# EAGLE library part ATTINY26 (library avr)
MICROCONTROLLER 2 Kbytes FLASH 128 bytes SRAM 128 bytes EEPROM USI 10-channel 10 bit ADC
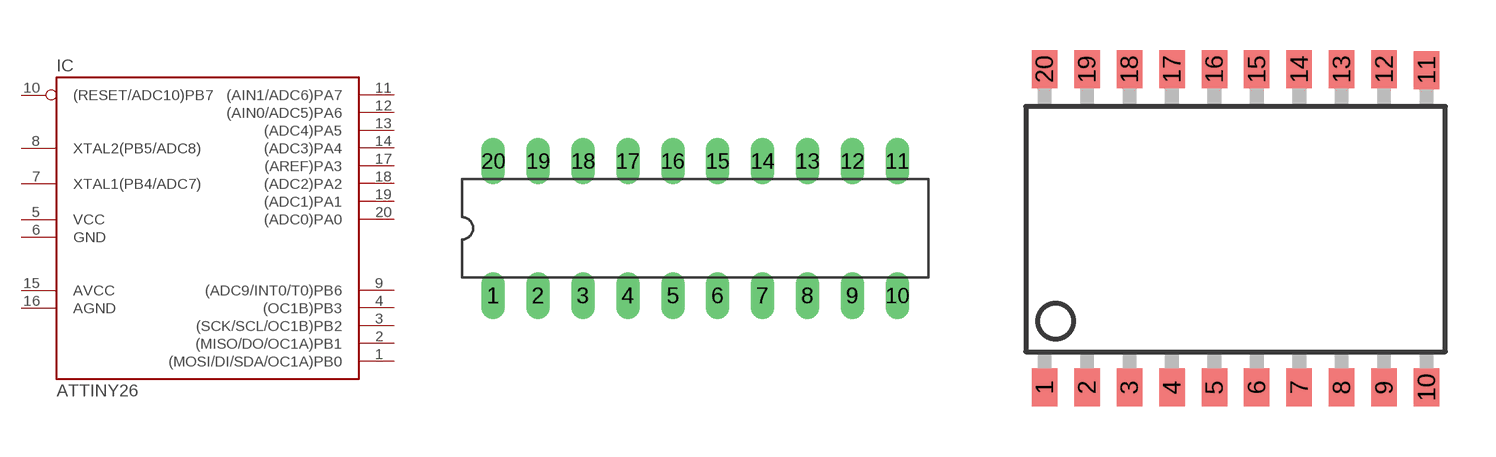
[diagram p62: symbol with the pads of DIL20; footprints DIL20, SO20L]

Designator prefix IC

## ATTINY26-16P, ATTINY26L-8P  [DIL20]
1  (MOSI/DI/SDA/OC1A)PB0
2  (MISO/DO/OC1A)PB1
3  (SCK/SCL/OC1B)PB2
4  (OC1B)PB3
5  VCC  pwr
6  GND  pwr
7  XTAL1(PB4/ADC7)
8  XTAL2(PB5/ADC8)
9  (ADC9/INT0/T0)PB6
10  (RESET/ADC10)PB7
11  (AIN1/ADC6)PA7
12  (AIN0/ADC5)PA6
13  (ADC4)PA5
14  (ADC3)PA4
15  AVCC  pwr
16  AGND  pwr
17  (AREF)PA3
18  (ADC2)PA2
19  (ADC1)PA1
20  (ADC0)PA0

## ATTINY26-16S, ATTINY26L-8S  [SO20L]
Pads as for DIL20

## Footprint DIL20 (pad centres in mm)
Dual In Line
drill 0.813 long: 1 -11.43,-3.81; 2 -8.89,-3.81; 3 -6.35,-3.81; 4 -3.81,-3.81; 5 -1.27,-3.81; 6 1.27,-3.81; 7 3.81,-3.81; 8 6.35,-3.81; 9 8.89,-3.81; 10 11.43,-3.81; 11 11.43,3.81; 12 8.89,3.81; 13 6.35,3.81; 14 3.81,3.81; 15 1.27,3.81; 16 -1.27,3.81; 17 -3.81,3.81; 18 -6.35,3.81; 19 -8.89,3.81; 20 -11.43,3.81

## Footprint SO20L (pad centres in mm)
Small Outline Package
smd 0.762 x 1.143: 1 -5.08,-5.131; 2 -3.81,-5.131; 3 -2.54,-5.131; 4 -1.27,-5.131; 5 0,-5.131; 6 1.27,-5.131; 7 2.54,-5.131; 8 3.81,-5.131; 9 5.08,-5.131; 10 6.35,-5.131; 11 6.35,4.369; 12 5.08,4.394; 13 3.81,4.394; 14 2.54,4.394; 15 1.27,4.394; 16 0,4.394; 17 -1.27,4.394; 18 -2.54,4.394; 19 -3.81,4.394; 20 -5.08,4.394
